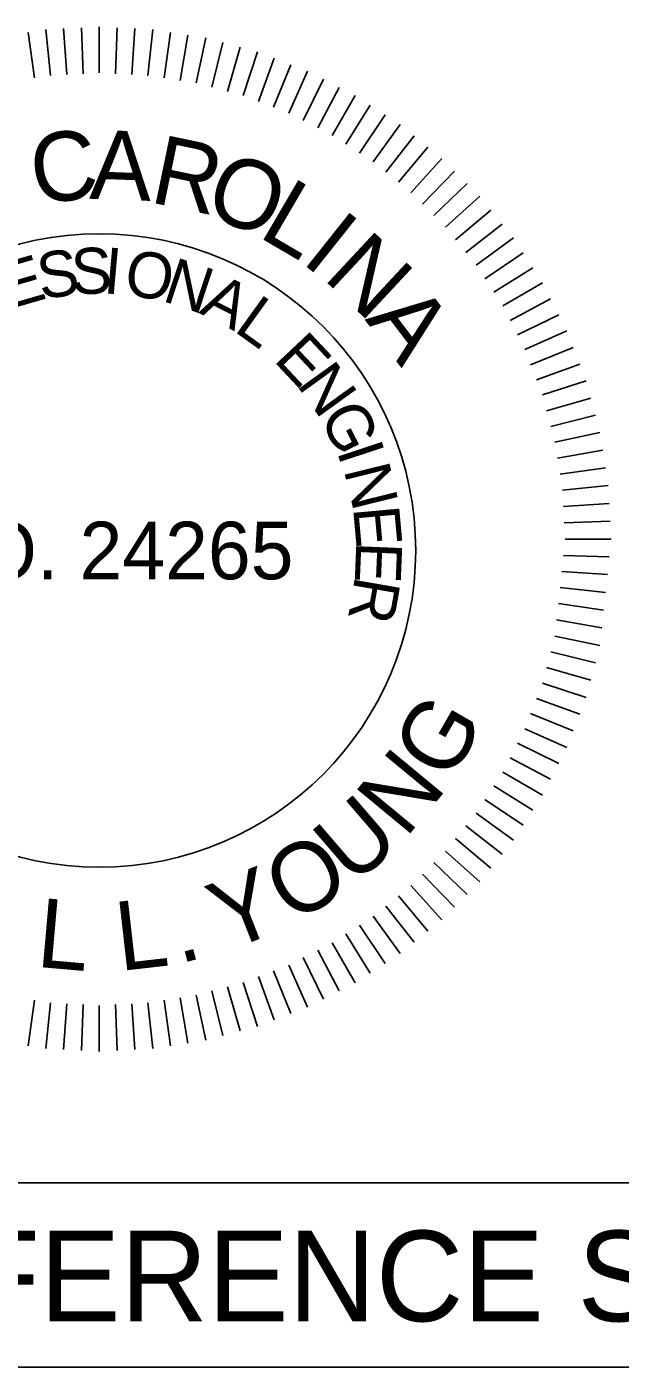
# Model space of a CAD drawing. Extents: x 1964849 to 1967422, y 1116563 to 1122211.
# Drawn here: x 1967322.6 to 1967368.5, y 1120529.2 to 1120632.8 of the extents above; entities that cross this region are included whole.
import ezdxf

# ---------------------------------------------------------------- set-up
doc = ezdxf.new("R2010")
doc.units = 0
doc.layers.add('RD_Sketch1', color=7, linetype='Continuous')
doc.layers.add('RD_TX_PEShield', color=7, linetype='Continuous')

msp = doc.modelspace()

# ---------------------------------------------------------------- linework, layer by layer
at = {"layer": 'RD_Sketch1'}
msp.add_lwpolyline([(1967105.7, 1120543.48), (1967406.12, 1120543.48), (1967406.12, 1120529.22), (1967105.7, 1120529.22)], close=True, dxfattribs=at)
at = {"layer": 'RD_TX_PEShield'}
for p, q in [((1967323.21, 1120628.89), (1967322.72, 1120632.41)), ((1967323.21, 1120628.89), (1967322.72, 1120632.41)), ((1967324.46, 1120629.09), (1967324.09, 1120632.63)), ((1967324.46, 1120629.09), (1967324.09, 1120632.63)), ((1967325.71, 1120629.15), (1967325.47, 1120632.7)), ((1967325.71, 1120629.15), (1967325.47, 1120632.7)), ((1967326.97, 1120629.22), (1967326.84, 1120632.77)), ((1967326.97, 1120629.22), (1967326.84, 1120632.77)), ((1967328.23, 1120629.28), (1967328.23, 1120632.84)), ((1967328.23, 1120629.28), (1967328.23, 1120632.84)), ((1967329.48, 1120629.22), (1967329.61, 1120632.77)), ((1967329.48, 1120629.22), (1967329.61, 1120632.77)), ((1967330.74, 1120629.15), (1967330.98, 1120632.7)), ((1967330.74, 1120629.15), (1967330.98, 1120632.7)), ((1967331.99, 1120629.09), (1967332.36, 1120632.63)), ((1967331.99, 1120629.09), (1967332.36, 1120632.63)), ((1967333.24, 1120628.89), (1967333.73, 1120632.41)), ((1967333.24, 1120628.89), (1967333.73, 1120632.41)), ((1967334.48, 1120628.69), (1967335.09, 1120632.19)), ((1967334.48, 1120628.69), (1967335.09, 1120632.19)), ((1967335.72, 1120628.5), (1967336.46, 1120631.98)), ((1967335.72, 1120628.5), (1967336.46, 1120631.98)), ((1967335.72, 1120628.5), (1967336.46, 1120631.98)), ((1967336.93, 1120628.17), (1967337.79, 1120631.62)), ((1967336.93, 1120628.17), (1967337.79, 1120631.62)), ((1967336.93, 1120628.17), (1967337.79, 1120631.62)), ((1967338.15, 1120627.84), (1967339.13, 1120631.26)), ((1967338.15, 1120627.84), (1967339.13, 1120631.26)), ((1967338.15, 1120627.84), (1967339.13, 1120631.26)), ((1967339.36, 1120627.52), (1967340.46, 1120630.9)), ((1967339.36, 1120627.52), (1967340.46, 1120630.9)), ((1967339.36, 1120627.52), (1967340.46, 1120630.9)), ((1967340.54, 1120627.07), (1967341.75, 1120630.41)), ((1967340.54, 1120627.07), (1967341.75, 1120630.41)), ((1967340.54, 1120627.07), (1967341.75, 1120630.41)), ((1967341.71, 1120626.62), (1967343.04, 1120629.91)), ((1967341.71, 1120626.62), (1967343.04, 1120629.91)), ((1967341.71, 1120626.62), (1967343.04, 1120629.91)), ((1967342.89, 1120626.17), (1967344.33, 1120629.42)), ((1967342.89, 1120626.17), (1967344.33, 1120629.42)), ((1967342.89, 1120626.17), (1967344.33, 1120629.42)), ((1967344.01, 1120625.6), (1967345.57, 1120628.79)), ((1967344.01, 1120625.6), (1967345.57, 1120628.79)), ((1967344.01, 1120625.6), (1967345.57, 1120628.79)), ((1967345.13, 1120625.03), (1967346.8, 1120628.16)), ((1967345.13, 1120625.03), (1967346.8, 1120628.16)), ((1967345.13, 1120625.03), (1967346.8, 1120628.16)), ((1967346.25, 1120624.45), (1967348.03, 1120627.54)), ((1967346.25, 1120624.45), (1967348.03, 1120627.54)), ((1967346.25, 1120624.45), (1967348.03, 1120627.54)), ((1967347.3, 1120623.77), (1967349.19, 1120626.78)), ((1967347.3, 1120623.77), (1967349.19, 1120626.78)), ((1967347.3, 1120623.77), (1967349.19, 1120626.78)), ((1967348.36, 1120623.08), (1967350.34, 1120626.03)), ((1967348.36, 1120623.08), (1967350.34, 1120626.03)), ((1967348.36, 1120623.08), (1967350.34, 1120626.03)), ((1967349.41, 1120622.4), (1967351.5, 1120625.28)), ((1967349.41, 1120622.4), (1967351.5, 1120625.28)), ((1967349.41, 1120622.4), (1967351.5, 1120625.28)), ((1967350.39, 1120621.61), (1967352.58, 1120624.41)), ((1967350.39, 1120621.61), (1967352.58, 1120624.41)), ((1967350.39, 1120621.61), (1967352.58, 1120624.41)), ((1967351.37, 1120620.82), (1967353.65, 1120623.54)), ((1967351.37, 1120620.82), (1967353.65, 1120623.54)), ((1967351.37, 1120620.82), (1967353.65, 1120623.54)), ((1967352.34, 1120620.02), (1967354.73, 1120622.67)), ((1967352.34, 1120620.02), (1967354.73, 1120622.67)), ((1967352.34, 1120620.02), (1967354.73, 1120622.67)), ((1967353.23, 1120619.14), (1967355.7, 1120621.69)), ((1967353.23, 1120619.14), (1967355.7, 1120621.69)), ((1967353.23, 1120619.14), (1967355.7, 1120621.69)), ((1967354.12, 1120618.25), (1967356.68, 1120620.72)), ((1967354.12, 1120618.25), (1967356.68, 1120620.72)), ((1967354.12, 1120618.25), (1967356.68, 1120620.72)), ((1967355.01, 1120617.36), (1967357.66, 1120619.74)), ((1967355.01, 1120617.36), (1967357.66, 1120619.74)), ((1967355.01, 1120617.36), (1967357.66, 1120619.74)), ((1967355.8, 1120616.38), (1967358.53, 1120618.66)), ((1967355.8, 1120616.38), (1967358.53, 1120618.66)), ((1967355.8, 1120616.38), (1967358.53, 1120618.66)), ((1967356.59, 1120615.4), (1967359.4, 1120617.59)), ((1967356.59, 1120615.4), (1967359.4, 1120617.59)), ((1967356.59, 1120615.4), (1967359.4, 1120617.59)), ((1967357.39, 1120614.42), (1967360.27, 1120616.52)), ((1967357.39, 1120614.42), (1967360.27, 1120616.52)), ((1967357.39, 1120614.42), (1967360.27, 1120616.52)), ((1967358.07, 1120613.37), (1967361.02, 1120615.36)), ((1967358.07, 1120613.37), (1967361.02, 1120615.36)), ((1967358.07, 1120613.37), (1967361.02, 1120615.36)), ((1967358.76, 1120612.32), (1967361.77, 1120614.2)), ((1967358.76, 1120612.32), (1967361.77, 1120614.2)), ((1967358.76, 1120612.32), (1967361.77, 1120614.2)), ((1967359.44, 1120611.26), (1967362.52, 1120613.04)), ((1967359.44, 1120611.26), (1967362.52, 1120613.04)), ((1967359.44, 1120611.26), (1967362.52, 1120613.04)), ((1967360.01, 1120610.14), (1967363.15, 1120611.81)), ((1967360.01, 1120610.14), (1967363.15, 1120611.81)), ((1967360.01, 1120610.14), (1967363.15, 1120611.81)), ((1967360.58, 1120609.02), (1967363.78, 1120610.58)), ((1967360.58, 1120609.02), (1967363.78, 1120610.58)), ((1967360.58, 1120609.02), (1967363.78, 1120610.58)), ((1967361.15, 1120607.9), (1967364.41, 1120609.35)), ((1967361.15, 1120607.9), (1967364.41, 1120609.35)), ((1967361.15, 1120607.9), (1967364.41, 1120609.35)), ((1967361.6, 1120606.72), (1967364.9, 1120608.06)), ((1967361.6, 1120606.72), (1967364.9, 1120608.06)), ((1967361.6, 1120606.72), (1967364.9, 1120608.06)), ((1967362.06, 1120605.55), (1967365.4, 1120606.77)), ((1967362.06, 1120605.55), (1967365.4, 1120606.77)), ((1967362.06, 1120605.55), (1967365.4, 1120606.77)), ((1967362.51, 1120604.38), (1967365.89, 1120605.48)), ((1967362.51, 1120604.38), (1967365.89, 1120605.48)), ((1967362.51, 1120604.38), (1967365.89, 1120605.48)), ((1967362.83, 1120603.16), (1967366.25, 1120604.14)), ((1967362.83, 1120603.16), (1967366.25, 1120604.14)), ((1967362.83, 1120603.16), (1967366.25, 1120604.14)), ((1967363.16, 1120601.95), (1967366.61, 1120602.81)), ((1967363.16, 1120601.95), (1967366.61, 1120602.81)), ((1967363.16, 1120601.95), (1967366.61, 1120602.81)), ((1967363.48, 1120600.73), (1967366.96, 1120601.47)), ((1967363.48, 1120600.73), (1967366.96, 1120601.47)), ((1967363.48, 1120600.73), (1967366.96, 1120601.47)), ((1967363.68, 1120599.49), (1967367.18, 1120600.11)), ((1967363.68, 1120599.49), (1967367.18, 1120600.11)), ((1967363.68, 1120599.49), (1967367.18, 1120600.11)), ((1967363.88, 1120598.25), (1967367.4, 1120598.74)), ((1967363.88, 1120598.25), (1967367.4, 1120598.74)), ((1967363.88, 1120598.25), (1967367.4, 1120598.74)), ((1967364.07, 1120597.01), (1967367.61, 1120597.38)), ((1967364.07, 1120597.01), (1967367.61, 1120597.38)), ((1967364.07, 1120597.01), (1967367.61, 1120597.38)), ((1967364.14, 1120595.75), (1967367.69, 1120596)), ((1967364.14, 1120595.75), (1967367.69, 1120596)), ((1967364.14, 1120595.75), (1967367.69, 1120596)), ((1967364.2, 1120594.49), (1967367.76, 1120594.62)), ((1967364.2, 1120594.49), (1967367.76, 1120594.62)), ((1967364.2, 1120594.49), (1967367.76, 1120594.62)), ((1967364.27, 1120593.24), (1967367.83, 1120593.24)), ((1967364.27, 1120593.24), (1967367.83, 1120593.24)), ((1967364.27, 1120593.24), (1967367.83, 1120593.24)), ((1967364.14, 1120591.98), (1967367.69, 1120591.86)), ((1967364.14, 1120591.98), (1967367.69, 1120591.86)), ((1967364.01, 1120590.74), (1967367.54, 1120590.49)), ((1967364.01, 1120590.74), (1967367.54, 1120590.49)), ((1967363.88, 1120589.49), (1967367.4, 1120589.12)), ((1967363.88, 1120589.49), (1967367.4, 1120589.12)), ((1967363.75, 1120588.25), (1967367.25, 1120587.75)), ((1967363.75, 1120588.25), (1967367.25, 1120587.75)), ((1967363.61, 1120587), (1967367.11, 1120586.38)), ((1967363.61, 1120587), (1967367.11, 1120586.38)), ((1967363.48, 1120585.74), (1967366.96, 1120585)), ((1967363.48, 1120585.74), (1967366.96, 1120585)), ((1967363.16, 1120584.53), (1967366.61, 1120583.67)), ((1967363.16, 1120584.53), (1967366.61, 1120583.67)), ((1967362.83, 1120583.31), (1967366.25, 1120582.33)), ((1967362.83, 1120583.31), (1967366.25, 1120582.33)), ((1967362.51, 1120582.1), (1967365.89, 1120581)), ((1967362.51, 1120582.1), (1967365.89, 1120581)), ((1967362.06, 1120580.92), (1967365.4, 1120579.71)), ((1967362.06, 1120580.92), (1967365.4, 1120579.71)), ((1967361.6, 1120579.75), (1967364.9, 1120578.42)), ((1967361.6, 1120579.75), (1967364.9, 1120578.42)), ((1967361.15, 1120578.58), (1967364.41, 1120577.13)), ((1967361.15, 1120578.58), (1967364.41, 1120577.13)), ((1967360.58, 1120577.46), (1967363.78, 1120575.9)), ((1967360.58, 1120577.46), (1967363.78, 1120575.9)), ((1967360.01, 1120576.34), (1967363.15, 1120574.67)), ((1967360.01, 1120576.34), (1967363.15, 1120574.67)), ((1967359.44, 1120575.22), (1967362.52, 1120573.44)), ((1967359.44, 1120575.22), (1967362.52, 1120573.44)), ((1967358.76, 1120574.16), (1967361.77, 1120572.28)), ((1967358.76, 1120574.16), (1967361.77, 1120572.28)), ((1967358.07, 1120573.11), (1967361.02, 1120571.12)), ((1967358.07, 1120573.11), (1967361.02, 1120571.12)), ((1967356.59, 1120571.07), (1967359.4, 1120568.88)), ((1967356.59, 1120571.07), (1967359.4, 1120568.88)), ((1967357.39, 1120572.05), (1967360.27, 1120569.96)), ((1967357.39, 1120572.05), (1967360.27, 1120569.96)), ((1967355.8, 1120570.1), (1967358.53, 1120567.81)), ((1967355.8, 1120570.1), (1967358.53, 1120567.81)), ((1967355.01, 1120569.12), (1967357.66, 1120566.74)), ((1967355.01, 1120569.12), (1967357.66, 1120566.74)), ((1967354.12, 1120568.23), (1967356.68, 1120565.76)), ((1967354.12, 1120568.23), (1967356.68, 1120565.76)), ((1967353.23, 1120567.34), (1967355.7, 1120564.78)), ((1967353.23, 1120567.34), (1967355.7, 1120564.78)), ((1967352.34, 1120566.45), (1967354.73, 1120563.81)), ((1967350.39, 1120564.87), (1967352.58, 1120562.07)), ((1967350.39, 1120564.87), (1967352.58, 1120562.07)), ((1967351.37, 1120565.66), (1967353.65, 1120562.94)), ((1967351.37, 1120565.66), (1967353.65, 1120562.94)), ((1967349.41, 1120564.08), (1967351.5, 1120561.2)), ((1967349.41, 1120564.08), (1967351.5, 1120561.2)), ((1967348.36, 1120563.39), (1967350.34, 1120560.44)), ((1967348.36, 1120563.39), (1967350.34, 1120560.44)), ((1967346.25, 1120562.02), (1967348.03, 1120558.94)), ((1967346.25, 1120562.02), (1967348.03, 1120558.94)), ((1967347.3, 1120562.71), (1967349.19, 1120559.69)), ((1967347.3, 1120562.71), (1967349.19, 1120559.69)), ((1967344.01, 1120560.88), (1967345.57, 1120557.68)), ((1967344.01, 1120560.88), (1967345.57, 1120557.68)), ((1967345.13, 1120561.45), (1967346.8, 1120558.31)), ((1967345.13, 1120561.45), (1967346.8, 1120558.31)), ((1967341.71, 1120559.86), (1967343.04, 1120556.56)), ((1967341.71, 1120559.86), (1967343.04, 1120556.56)), ((1967342.89, 1120560.31), (1967344.33, 1120557.06)), ((1967342.89, 1120560.31), (1967344.33, 1120557.06)), ((1967338.15, 1120558.63), (1967339.13, 1120555.21)), ((1967338.15, 1120558.63), (1967339.13, 1120555.21)), ((1967339.36, 1120558.96), (1967340.46, 1120555.57)), ((1967339.36, 1120558.96), (1967340.46, 1120555.57)), ((1967340.54, 1120559.41), (1967341.75, 1120556.07)), ((1967340.54, 1120559.41), (1967341.75, 1120556.07)), ((1967334.48, 1120557.78), (1967335.09, 1120554.28)), ((1967334.48, 1120557.78), (1967335.09, 1120554.28)), ((1967335.72, 1120557.98), (1967336.46, 1120554.5)), ((1967335.72, 1120557.98), (1967336.46, 1120554.5)), ((1967336.93, 1120558.31), (1967337.79, 1120554.86)), ((1967336.93, 1120558.31), (1967337.79, 1120554.86)), ((1967323.21, 1120557.59), (1967322.72, 1120554.07)), ((1967323.21, 1120557.59), (1967322.72, 1120554.07)), ((1967324.46, 1120557.39), (1967324.09, 1120553.85)), ((1967324.46, 1120557.39), (1967324.09, 1120553.85)), ((1967325.71, 1120557.32), (1967325.47, 1120553.78)), ((1967325.71, 1120557.32), (1967325.47, 1120553.78)), ((1967326.97, 1120557.26), (1967326.84, 1120553.71)), ((1967326.97, 1120557.26), (1967326.84, 1120553.71)), ((1967328.23, 1120557.19), (1967328.23, 1120553.63)), ((1967328.23, 1120557.19), (1967328.23, 1120553.63)), ((1967329.48, 1120557.26), (1967329.61, 1120553.71)), ((1967329.48, 1120557.26), (1967329.61, 1120553.71)), ((1967330.74, 1120557.32), (1967330.98, 1120553.78)), ((1967330.74, 1120557.32), (1967330.98, 1120553.78)), ((1967331.99, 1120557.39), (1967332.36, 1120553.85)), ((1967331.99, 1120557.39), (1967332.36, 1120553.85)), ((1967333.24, 1120557.59), (1967333.73, 1120554.07)), ((1967333.24, 1120557.59), (1967333.73, 1120554.07))]:
    msp.add_line(p, q, dxfattribs=at)
msp.add_circle((1967328.23, 1120592.36), 24.48, dxfattribs=at)

# ---------------------------------------------------------------- texts
at = {"layer": 'RD_Sketch1'}
msp.add_text('ALIGNMENT CONTROL CAN BE FOUND ON REFERENCE SHEET', height=7, dxfattribs=at).set_placement((1967109.35, 1120532.77))
at = {"layer": 'RD_TX_PEShield'}
for s, height, rotation, p in [('C', 5.34, 6.8832, (1967323.22, 1120619.1)), ('A', 5.34, 357.9448, (1967327.43, 1120619.55)), ('R', 5.34, 348.267, (1967332.02, 1120619.3)), ('O', 5.34, 339.3286, (1967336.16, 1120618.38)), ('L', 5.34, 329.6507, (1967340.42, 1120616.68)), ('I', 5.34, 321.4663, (1967343.75, 1120614.69)), ('N', 5.34, 317.0007, (1967345.45, 1120613.42)), ('S', 3.56, 8.6909, (1967323.71, 1120611.75)), ('S', 3.56, 1.79, (1967326.08, 1120612.15)), ('I', 3.56, 354.889, (1967328.47, 1120612.26)), ('E', 3.56, 16.1843, (1967321.22, 1120610.99)), ('O', 3.56, 350.4045, (1967330.02, 1120612.18)), ('N', 3.56, 341.7029, (1967333, 1120611.68)), ('A', 3.56, 333.0013, (1967335.87, 1120610.74)), ('L', 3.56, 324.2997, (1967338.56, 1120609.37)), ('A', 5.34, 307.3229, (1967348.74, 1120610.22)), ('E', 3.56, 313.2251, (1967341.64, 1120607.07)), ('N', 3.56, 305.7317, (1967343.44, 1120605.19)), ('G', 3.56, 297.0301, (1967345.21, 1120602.74)), ('I', 3.56, 288.3285, (1967346.58, 1120600.05)), ('N', 3.56, 283.8441, (1967347.13, 1120598.6)), ('E', 3.56, 275.1424, (1967347.86, 1120595.66)), ('E', 3.56, 267.6491, (1967348.12, 1120593.08)), ('R', 3.56, 260.1557, (1967348.04, 1120590.47)), ('G', 5.34, 60.1113, (1967355.33, 1120574.34)), ('N', 5.34, 50.4335, (1967351.92, 1120570.04)), ('U', 5.34, 40.7556, (1967347.83, 1120566.37)), ('O', 5.34, 31.0778, (1967343.18, 1120563.44)), ('Y', 5.34, 21.4, (1967338.11, 1120561.34)), ('L', 5.34, 354.9835, (1967323.28, 1120560.18)), ('L', 5.34, 6.5171, (1967329.81, 1120559.84)), ('.', 5.34, 14.7016, (1967334.42, 1120560.4))]:
    msp.add_text(s, height=height, rotation=rotation, dxfattribs=at).set_placement(p)
msp.add_text('NO. 24265', height=4.45, dxfattribs=at).set_placement((1967314.47, 1120590.13))

doc.saveas('drawing.dxf')
